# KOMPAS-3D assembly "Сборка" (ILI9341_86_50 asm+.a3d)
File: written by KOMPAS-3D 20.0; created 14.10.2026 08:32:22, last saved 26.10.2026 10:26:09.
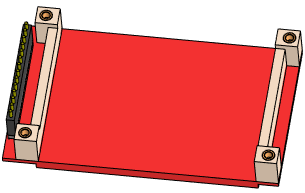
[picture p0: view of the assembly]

Document properties: Полное имя файла: D:\RicWork\Project-EPS32\box_compas\монитор\ILI9341_86_50 asm+.a3d

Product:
- Part/product: Сборка
    Масса: 0.11309
  - Component [assembly]: Сборка  | qty 2  | Масса: 0.0139528; source file: ..\корпус\п-стойка_1 asm.a3d
  - Component [detail]: Деталь  | Масса: 0.00428927; source file: ..\разъемы\pbs_14.m3d
  - Component [detail]: Деталь  | Масса: 0.00182492; source file: ..\разъемы\pls_14.m3d
  - Component [detail]: Деталь  | Масса: 0.0790697; source file: ILI9341_86_50.m3d

Referenced files in D:\RicWork\Project-EPS32\box_compas\монитор\: ILI9341_86_50.m3d
Referenced files in D:\RicWork\Project-EPS32\box_compas\разъемы\: pls_14.m3d, pbs_14.m3d
Referenced files in D:\RicWork\Project-EPS32\box_compas\корпус\: п-стойка_1 asm.a3d
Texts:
  Сборка (1)
  Сборка (2)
